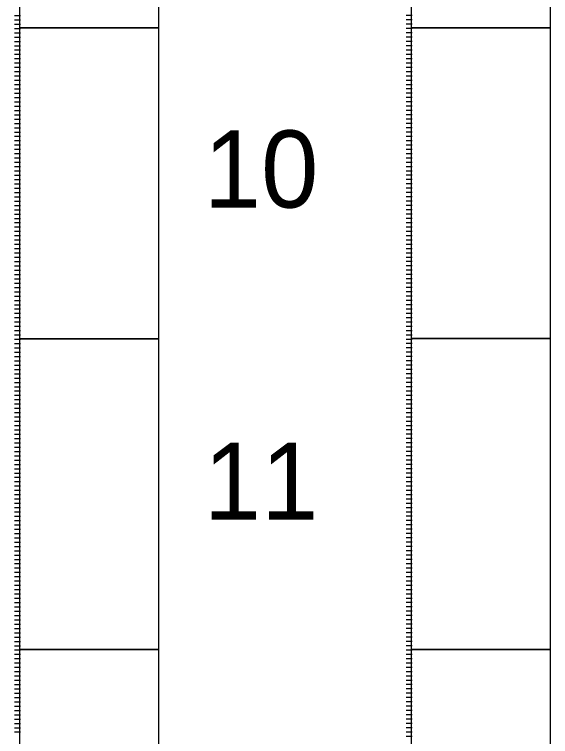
# Model space of a CAD drawing. Extents: x 12316 to 12541, y 1124 to 1850.
# Drawn here: x 12431.01 to 12465.81, y 1620.54 to 1667.39 of the extents above; entities that cross this region are included whole.
import ezdxf

# ---------------------------------------------------------------- set-up
doc = ezdxf.new("R2010")
doc.units = 0
doc.layers.add('SC_Scratch1', color=7, linetype='Continuous')
doc.layers.add('SH_Text', color=7, linetype='Continuous')

msp = doc.modelspace()

# ---------------------------------------------------------------- linework, layer by layer
at = {"layer": 'SC_Scratch1'}
for p, q in [((12431.394, 1667.297), (12431.01, 1667.297)), ((12456.827, 1667.309), (12456.443, 1667.309)), ((12431.394, 1667.017), (12431.01, 1667.017)), ((12431.394, 1666.737), (12431.01, 1666.737)), ((12456.827, 1667.029), (12456.443, 1667.029)), ((12456.827, 1666.749), (12456.443, 1666.749)), ((12431.394, 1666.457), (12431.01, 1666.457)), ((12456.827, 1666.469), (12456.443, 1666.469)), ((12456.827, 1666.189), (12456.443, 1666.189)), ((12431.394, 1666.177), (12431.01, 1666.177)), ((12431.394, 1665.897), (12431.01, 1665.897)), ((12456.827, 1665.909), (12456.443, 1665.909)), ((12431.394, 1665.617), (12431.01, 1665.617)), ((12431.394, 1665.337), (12431.01, 1665.337)), ((12456.827, 1665.629), (12456.443, 1665.629)), ((12456.827, 1665.349), (12456.443, 1665.349)), ((12431.394, 1665.057), (12431.01, 1665.057)), ((12431.394, 1664.777), (12431.01, 1664.777)), ((12456.827, 1665.069), (12456.443, 1665.069)), ((12456.827, 1664.789), (12456.443, 1664.789)), ((12431.394, 1664.497), (12431.01, 1664.497)), ((12456.827, 1664.509), (12456.443, 1664.509)), ((12431.394, 1664.217), (12431.01, 1664.217)), ((12431.394, 1663.937), (12431.01, 1663.937)), ((12456.827, 1664.229), (12456.443, 1664.229)), ((12456.827, 1663.949), (12456.443, 1663.949)), ((12431.394, 1663.657), (12431.01, 1663.657)), ((12431.394, 1663.377), (12431.01, 1663.377)), ((12456.827, 1663.669), (12456.443, 1663.669)), ((12456.827, 1663.389), (12456.443, 1663.389)), ((12431.394, 1663.097), (12431.01, 1663.097)), ((12456.827, 1663.109), (12456.443, 1663.109)), ((12431.394, 1662.817), (12431.01, 1662.817)), ((12431.394, 1662.537), (12431.01, 1662.537)), ((12456.827, 1662.829), (12456.443, 1662.829)), ((12456.827, 1662.549), (12456.443, 1662.549)), ((12431.394, 1662.257), (12431.01, 1662.257)), ((12431.394, 1661.977), (12431.01, 1661.977)), ((12456.827, 1662.269), (12456.443, 1662.269)), ((12456.827, 1661.989), (12456.443, 1661.989)), ((12431.394, 1661.697), (12431.01, 1661.697)), ((12456.827, 1661.709), (12456.443, 1661.709)), ((12431.394, 1661.417), (12431.01, 1661.417)), ((12431.394, 1661.137), (12431.01, 1661.137)), ((12456.827, 1661.429), (12456.443, 1661.429)), ((12456.827, 1661.149), (12456.443, 1661.149)), ((12431.394, 1660.857), (12431.01, 1660.857)), ((12431.394, 1660.577), (12431.01, 1660.577)), ((12456.827, 1660.869), (12456.443, 1660.869)), ((12456.827, 1660.589), (12456.443, 1660.589)), ((12431.394, 1660.297), (12431.01, 1660.297)), ((12456.827, 1660.309), (12456.443, 1660.309)), ((12431.394, 1660.017), (12431.01, 1660.017)), ((12431.394, 1659.737), (12431.01, 1659.737)), ((12456.827, 1660.029), (12456.443, 1660.029)), ((12456.827, 1659.749), (12456.443, 1659.749)), ((12431.394, 1659.457), (12431.01, 1659.457)), ((12431.394, 1659.177), (12431.01, 1659.177)), ((12456.827, 1659.469), (12456.443, 1659.469)), ((12456.827, 1659.189), (12456.443, 1659.189)), ((12431.394, 1658.897), (12431.01, 1658.897)), ((12456.827, 1658.909), (12456.443, 1658.909)), ((12431.394, 1658.617), (12431.01, 1658.617)), ((12431.394, 1658.337), (12431.01, 1658.337)), ((12456.827, 1658.629), (12456.443, 1658.629)), ((12456.827, 1658.349), (12456.443, 1658.349)), ((12431.394, 1658.057), (12431.01, 1658.057)), ((12431.394, 1657.777), (12431.01, 1657.777)), ((12456.827, 1658.069), (12456.443, 1658.069)), ((12456.827, 1657.789), (12456.443, 1657.789)), ((12431.394, 1657.497), (12431.01, 1657.497)), ((12456.827, 1657.509), (12456.443, 1657.509)), ((12431.394, 1657.217), (12431.01, 1657.217)), ((12431.394, 1656.937), (12431.01, 1656.937)), ((12456.827, 1657.229), (12456.443, 1657.229)), ((12456.827, 1656.949), (12456.443, 1656.949)), ((12431.394, 1656.657), (12431.01, 1656.657)), ((12431.394, 1656.377), (12431.01, 1656.377)), ((12456.827, 1656.669), (12456.443, 1656.669)), ((12456.827, 1656.389), (12456.443, 1656.389)), ((12431.394, 1656.097), (12431.01, 1656.097)), ((12456.827, 1656.109), (12456.443, 1656.109)), ((12431.394, 1655.817), (12431.01, 1655.817)), ((12431.394, 1655.537), (12431.01, 1655.537)), ((12456.827, 1655.829), (12456.443, 1655.829)), ((12456.827, 1655.549), (12456.443, 1655.549)), ((12431.394, 1655.257), (12431.01, 1655.257)), ((12431.394, 1654.977), (12431.01, 1654.977)), ((12456.827, 1655.269), (12456.443, 1655.269)), ((12456.827, 1654.989), (12456.443, 1654.989)), ((12431.394, 1654.697), (12431.01, 1654.697)), ((12456.827, 1654.709), (12456.443, 1654.709)), ((12431.394, 1654.417), (12431.01, 1654.417)), ((12431.394, 1654.137), (12431.01, 1654.137)), ((12456.827, 1654.429), (12456.443, 1654.429)), ((12456.827, 1654.149), (12456.443, 1654.149)), ((12431.394, 1653.857), (12431.01, 1653.857)), ((12431.394, 1653.577), (12431.01, 1653.577)), ((12456.827, 1653.869), (12456.443, 1653.869)), ((12456.827, 1653.589), (12456.443, 1653.589)), ((12431.394, 1653.297), (12431.01, 1653.297)), ((12456.827, 1653.309), (12456.443, 1653.309)), ((12431.394, 1653.017), (12431.01, 1653.017)), ((12431.394, 1652.737), (12431.01, 1652.737)), ((12456.827, 1653.029), (12456.443, 1653.029)), ((12456.827, 1652.749), (12456.443, 1652.749)), ((12431.394, 1652.457), (12431.01, 1652.457)), ((12431.394, 1652.177), (12431.01, 1652.177)), ((12456.827, 1652.469), (12456.443, 1652.469)), ((12456.827, 1652.189), (12456.443, 1652.189)), ((12431.394, 1651.897), (12431.01, 1651.897)), ((12456.827, 1651.909), (12456.443, 1651.909)), ((12431.394, 1651.617), (12431.01, 1651.617)), ((12431.394, 1651.337), (12431.01, 1651.337)), ((12456.827, 1651.629), (12456.443, 1651.629)), ((12456.827, 1651.349), (12456.443, 1651.349)), ((12431.394, 1651.057), (12431.01, 1651.057)), ((12431.394, 1650.777), (12431.01, 1650.777)), ((12456.827, 1651.069), (12456.443, 1651.069)), ((12456.827, 1650.789), (12456.443, 1650.789)), ((12431.394, 1650.497), (12431.01, 1650.497)), ((12456.827, 1650.509), (12456.443, 1650.509)), ((12431.394, 1650.217), (12431.01, 1650.217)), ((12431.394, 1649.937), (12431.01, 1649.937)), ((12456.827, 1650.229), (12456.443, 1650.229)), ((12456.827, 1649.949), (12456.443, 1649.949)), ((12431.394, 1649.657), (12431.01, 1649.657)), ((12431.394, 1649.377), (12431.01, 1649.377)), ((12456.827, 1649.669), (12456.443, 1649.669)), ((12456.827, 1649.389), (12456.443, 1649.389)), ((12431.394, 1649.097), (12431.01, 1649.097)), ((12456.827, 1649.109), (12456.443, 1649.109)), ((12431.394, 1648.817), (12431.01, 1648.817)), ((12431.394, 1648.537), (12431.01, 1648.537)), ((12456.827, 1648.829), (12456.443, 1648.829)), ((12456.827, 1648.549), (12456.443, 1648.549)), ((12431.394, 1648.257), (12431.01, 1648.257)), ((12431.394, 1647.977), (12431.01, 1647.977)), ((12456.827, 1648.269), (12456.443, 1648.269)), ((12456.827, 1647.989), (12456.443, 1647.989)), ((12431.394, 1647.697), (12431.01, 1647.697)), ((12456.827, 1647.709), (12456.443, 1647.709)), ((12431.394, 1647.417), (12431.01, 1647.417)), ((12431.394, 1647.137), (12431.01, 1647.137)), ((12456.827, 1647.429), (12456.443, 1647.429)), ((12456.827, 1647.149), (12456.443, 1647.149)), ((12431.394, 1646.857), (12431.01, 1646.857)), ((12431.394, 1646.577), (12431.01, 1646.577)), ((12456.827, 1646.869), (12456.443, 1646.869)), ((12456.827, 1646.589), (12456.443, 1646.589)), ((12431.394, 1646.297), (12431.01, 1646.297)), ((12456.827, 1646.309), (12456.443, 1646.309)), ((12431.394, 1646.017), (12431.01, 1646.017)), ((12431.394, 1645.737), (12431.01, 1645.737)), ((12456.827, 1646.029), (12456.443, 1646.029)), ((12456.827, 1645.749), (12456.443, 1645.749)), ((12431.394, 1645.457), (12431.01, 1645.457)), ((12431.394, 1645.177), (12431.01, 1645.177)), ((12456.827, 1645.469), (12456.443, 1645.469)), ((12456.827, 1645.189), (12456.443, 1645.189)), ((12431.394, 1644.897), (12431.01, 1644.897)), ((12456.827, 1644.909), (12456.443, 1644.909)), ((12431.394, 1644.617), (12431.01, 1644.617)), ((12431.394, 1644.337), (12431.01, 1644.337)), ((12456.827, 1644.629), (12456.443, 1644.629)), ((12456.827, 1644.349), (12456.443, 1644.349)), ((12431.394, 1644.057), (12431.01, 1644.057)), ((12431.394, 1643.777), (12431.01, 1643.777)), ((12456.827, 1644.069), (12456.443, 1644.069)), ((12456.827, 1643.789), (12456.443, 1643.789)), ((12431.394, 1643.497), (12431.01, 1643.497)), ((12456.827, 1643.509), (12456.443, 1643.509)), ((12456.827, 1643.229), (12456.443, 1643.229)), ((12431.394, 1643.217), (12431.01, 1643.217)), ((12431.394, 1642.937), (12431.01, 1642.937)), ((12456.827, 1642.949), (12456.443, 1642.949)), ((12431.394, 1642.657), (12431.01, 1642.657)), ((12431.394, 1642.377), (12431.01, 1642.377)), ((12456.827, 1642.669), (12456.443, 1642.669)), ((12456.827, 1642.389), (12456.443, 1642.389)), ((12431.394, 1642.097), (12431.01, 1642.097)), ((12456.827, 1642.109), (12456.443, 1642.109)), ((12456.827, 1641.829), (12456.443, 1641.829)), ((12431.394, 1641.817), (12431.01, 1641.817)), ((12431.394, 1641.537), (12431.01, 1641.537)), ((12456.827, 1641.549), (12456.443, 1641.549)), ((12431.394, 1641.257), (12431.01, 1641.257)), ((12431.394, 1640.977), (12431.01, 1640.977)), ((12456.827, 1641.269), (12456.443, 1641.269)), ((12456.827, 1640.989), (12456.443, 1640.989)), ((12431.394, 1640.697), (12431.01, 1640.697)), ((12431.394, 1640.417), (12431.01, 1640.417)), ((12456.827, 1640.709), (12456.443, 1640.709)), ((12456.827, 1640.429), (12456.443, 1640.429)), ((12431.394, 1640.137), (12431.01, 1640.137)), ((12456.827, 1640.149), (12456.443, 1640.149)), ((12431.394, 1639.857), (12431.01, 1639.857)), ((12431.394, 1639.577), (12431.01, 1639.577)), ((12456.827, 1639.869), (12456.443, 1639.869)), ((12456.827, 1639.589), (12456.443, 1639.589)), ((12431.394, 1639.297), (12431.01, 1639.297)), ((12431.394, 1639.017), (12431.01, 1639.017)), ((12456.827, 1639.309), (12456.443, 1639.309)), ((12456.827, 1639.029), (12456.443, 1639.029)), ((12431.394, 1638.737), (12431.01, 1638.737)), ((12456.827, 1638.749), (12456.443, 1638.749)), ((12431.394, 1638.457), (12431.01, 1638.457)), ((12431.394, 1638.177), (12431.01, 1638.177)), ((12456.827, 1638.469), (12456.443, 1638.469)), ((12456.827, 1638.189), (12456.443, 1638.189)), ((12431.394, 1637.897), (12431.01, 1637.897)), ((12431.394, 1637.617), (12431.01, 1637.617)), ((12456.827, 1637.909), (12456.443, 1637.909)), ((12456.827, 1637.629), (12456.443, 1637.629)), ((12431.394, 1637.337), (12431.01, 1637.337)), ((12456.827, 1637.349), (12456.443, 1637.349)), ((12431.394, 1637.057), (12431.01, 1637.057)), ((12431.394, 1636.777), (12431.01, 1636.777)), ((12456.827, 1637.069), (12456.443, 1637.069)), ((12456.827, 1636.789), (12456.443, 1636.789)), ((12431.394, 1636.497), (12431.01, 1636.497)), ((12431.394, 1636.217), (12431.01, 1636.217)), ((12456.827, 1636.509), (12456.443, 1636.509)), ((12456.827, 1636.229), (12456.443, 1636.229)), ((12431.394, 1635.937), (12431.01, 1635.937)), ((12456.827, 1635.949), (12456.443, 1635.949)), ((12431.394, 1635.657), (12431.01, 1635.657)), ((12431.394, 1635.377), (12431.01, 1635.377)), ((12456.827, 1635.669), (12456.443, 1635.669)), ((12456.827, 1635.389), (12456.443, 1635.389)), ((12431.394, 1635.097), (12431.01, 1635.097)), ((12431.394, 1634.817), (12431.01, 1634.817)), ((12456.827, 1635.109), (12456.443, 1635.109)), ((12456.827, 1634.829), (12456.443, 1634.829)), ((12431.394, 1634.537), (12431.01, 1634.537)), ((12456.827, 1634.549), (12456.443, 1634.549)), ((12431.394, 1634.257), (12431.01, 1634.257)), ((12431.394, 1633.977), (12431.01, 1633.977)), ((12456.827, 1634.269), (12456.443, 1634.269)), ((12456.827, 1633.989), (12456.443, 1633.989)), ((12431.394, 1633.697), (12431.01, 1633.697)), ((12431.394, 1633.417), (12431.01, 1633.417)), ((12456.827, 1633.709), (12456.443, 1633.709)), ((12456.827, 1633.429), (12456.443, 1633.429)), ((12431.394, 1633.137), (12431.01, 1633.137)), ((12456.827, 1633.149), (12456.443, 1633.149)), ((12431.394, 1632.857), (12431.01, 1632.857)), ((12431.394, 1632.577), (12431.01, 1632.577)), ((12456.827, 1632.869), (12456.443, 1632.869)), ((12456.827, 1632.589), (12456.443, 1632.589)), ((12431.394, 1632.297), (12431.01, 1632.297)), ((12431.394, 1632.017), (12431.01, 1632.017)), ((12456.827, 1632.309), (12456.443, 1632.309)), ((12456.827, 1632.029), (12456.443, 1632.029)), ((12431.394, 1631.737), (12431.01, 1631.737)), ((12456.827, 1631.749), (12456.443, 1631.749)), ((12431.394, 1631.457), (12431.01, 1631.457)), ((12431.394, 1631.177), (12431.01, 1631.177)), ((12456.827, 1631.469), (12456.443, 1631.469)), ((12456.827, 1631.189), (12456.443, 1631.189)), ((12431.394, 1630.897), (12431.01, 1630.897)), ((12431.394, 1630.617), (12431.01, 1630.617)), ((12456.827, 1630.909), (12456.443, 1630.909)), ((12456.827, 1630.629), (12456.443, 1630.629)), ((12431.394, 1630.337), (12431.01, 1630.337)), ((12456.827, 1630.349), (12456.443, 1630.349)), ((12431.394, 1630.057), (12431.01, 1630.057)), ((12431.394, 1629.777), (12431.01, 1629.777)), ((12456.827, 1630.069), (12456.443, 1630.069)), ((12456.827, 1629.789), (12456.443, 1629.789)), ((12431.394, 1629.497), (12431.01, 1629.497)), ((12431.394, 1629.217), (12431.01, 1629.217)), ((12456.827, 1629.509), (12456.443, 1629.509)), ((12456.827, 1629.229), (12456.443, 1629.229)), ((12431.394, 1628.937), (12431.01, 1628.937)), ((12456.827, 1628.949), (12456.443, 1628.949)), ((12431.394, 1628.657), (12431.01, 1628.657)), ((12431.394, 1628.377), (12431.01, 1628.377)), ((12456.827, 1628.669), (12456.443, 1628.669)), ((12456.827, 1628.389), (12456.443, 1628.389)), ((12431.394, 1628.097), (12431.01, 1628.097)), ((12431.394, 1627.817), (12431.01, 1627.817)), ((12456.827, 1628.109), (12456.443, 1628.109)), ((12456.827, 1627.829), (12456.443, 1627.829)), ((12431.394, 1627.537), (12431.01, 1627.537)), ((12456.827, 1627.549), (12456.443, 1627.549)), ((12431.394, 1627.257), (12431.01, 1627.257)), ((12431.394, 1626.977), (12431.01, 1626.977)), ((12456.827, 1627.269), (12456.443, 1627.269)), ((12456.827, 1626.989), (12456.443, 1626.989)), ((12431.394, 1626.697), (12431.01, 1626.697)), ((12431.394, 1626.417), (12431.01, 1626.417)), ((12456.827, 1626.709), (12456.443, 1626.709)), ((12456.827, 1626.429), (12456.443, 1626.429)), ((12431.394, 1626.137), (12431.01, 1626.137)), ((12456.827, 1626.149), (12456.443, 1626.149)), ((12431.394, 1625.857), (12431.01, 1625.857)), ((12431.394, 1625.577), (12431.01, 1625.577)), ((12456.827, 1625.869), (12456.443, 1625.869)), ((12456.827, 1625.589), (12456.443, 1625.589)), ((12431.394, 1625.297), (12431.01, 1625.297)), ((12431.394, 1625.017), (12431.01, 1625.017)), ((12456.827, 1625.309), (12456.443, 1625.309)), ((12456.827, 1625.029), (12456.443, 1625.029)), ((12431.394, 1624.737), (12431.01, 1624.737)), ((12456.827, 1624.749), (12456.443, 1624.749)), ((12431.394, 1624.457), (12431.01, 1624.457)), ((12431.394, 1624.177), (12431.01, 1624.177)), ((12456.827, 1624.469), (12456.443, 1624.469)), ((12456.827, 1624.189), (12456.443, 1624.189)), ((12431.394, 1623.897), (12431.01, 1623.897)), ((12431.394, 1623.617), (12431.01, 1623.617)), ((12456.827, 1623.909), (12456.443, 1623.909)), ((12456.827, 1623.629), (12456.443, 1623.629)), ((12431.394, 1623.337), (12431.01, 1623.337)), ((12456.827, 1623.349), (12456.443, 1623.349)), ((12431.394, 1623.057), (12431.01, 1623.057)), ((12431.394, 1622.777), (12431.01, 1622.777)), ((12456.827, 1623.069), (12456.443, 1623.069)), ((12456.827, 1622.789), (12456.443, 1622.789)), ((12431.394, 1622.497), (12431.01, 1622.497)), ((12431.394, 1622.217), (12431.01, 1622.217)), ((12456.827, 1622.509), (12456.443, 1622.509)), ((12456.827, 1622.229), (12456.443, 1622.229)), ((12431.394, 1621.937), (12431.01, 1621.937)), ((12456.827, 1621.949), (12456.443, 1621.949)), ((12431.394, 1621.657), (12431.01, 1621.657)), ((12431.394, 1621.377), (12431.01, 1621.377)), ((12456.827, 1621.669), (12456.443, 1621.669)), ((12456.827, 1621.389), (12456.443, 1621.389)), ((12431.394, 1621.097), (12431.01, 1621.097)), ((12431.394, 1620.817), (12431.01, 1620.817)), ((12456.827, 1621.109), (12456.443, 1621.109)), ((12456.827, 1620.829), (12456.443, 1620.829)), ((12456.827, 1620.549), (12456.443, 1620.549))]:
    msp.add_line(p, q, dxfattribs=at)
for points in [[(12440.38, 1686.667), (12431.337, 1686.667), (12431.337, 1666.507), (12440.38, 1666.507)], [(12465.813, 1686.679), (12456.77, 1686.679), (12456.77, 1666.519), (12465.813, 1666.519)], [(12440.38, 1666.507), (12431.337, 1666.507), (12431.337, 1646.347), (12440.38, 1646.347)], [(12465.813, 1666.519), (12456.77, 1666.519), (12456.77, 1646.359), (12465.813, 1646.359)], [(12440.38, 1646.347), (12431.337, 1646.347), (12431.337, 1626.187), (12440.38, 1626.187)], [(12465.813, 1646.359), (12456.77, 1646.359), (12456.77, 1626.199), (12465.813, 1626.199)], [(12440.38, 1626.187), (12431.337, 1626.187), (12431.337, 1606.027), (12440.38, 1606.027)], [(12465.813, 1626.199), (12456.77, 1626.199), (12456.77, 1606.039), (12465.813, 1606.039)]]:
    msp.add_lwpolyline(points, close=True, dxfattribs=at)

# ---------------------------------------------------------------- texts
at = {"layer": 'SH_Text'}
for s, p in [('10', (12443.304, 1654.857)), ('11', (12443.304, 1634.604))]:
    msp.add_text(s, height=5, dxfattribs=at).set_placement(p)

doc.saveas('drawing.dxf')
